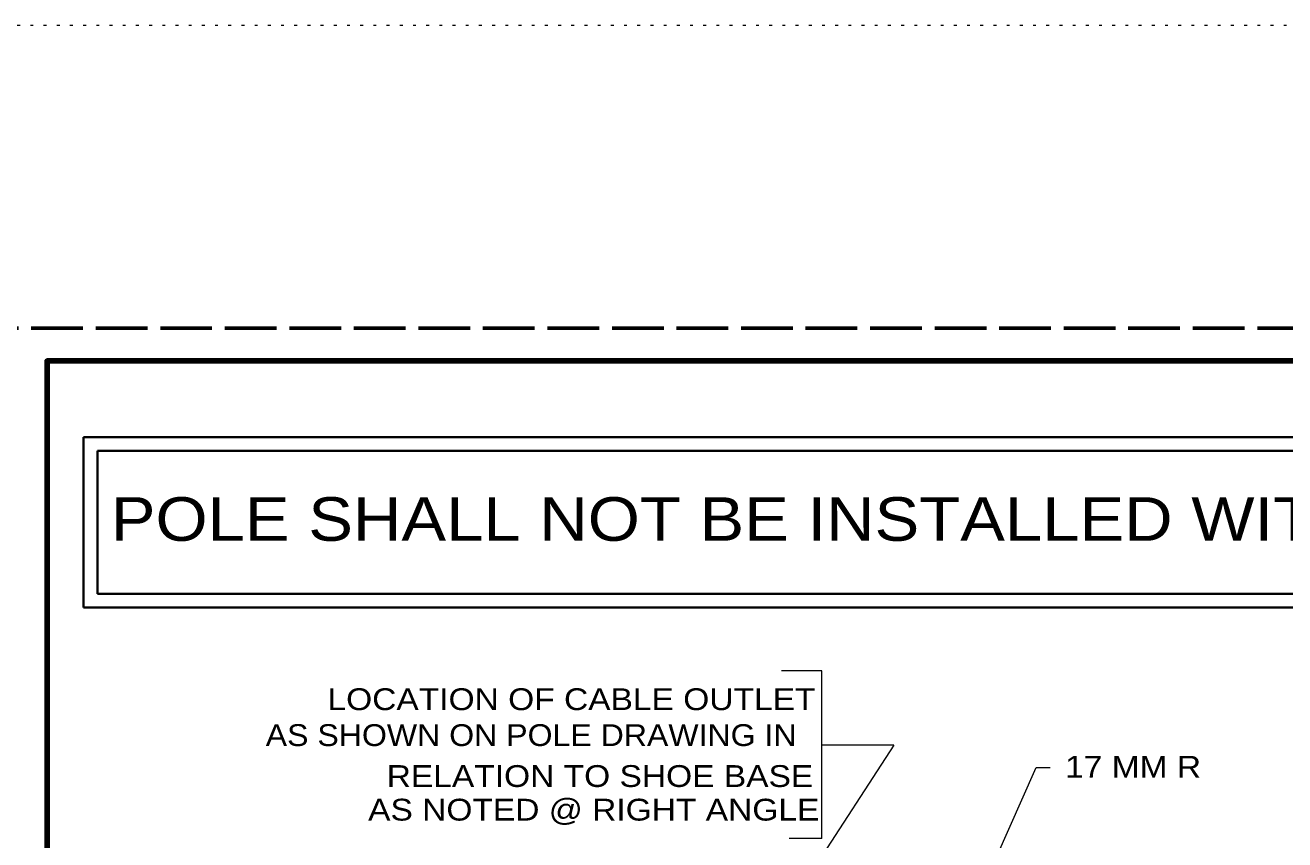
# Model space of a CAD drawing. Extents: x 312583 to 312854, y 144419 to 144597.
# Drawn here: x 312615.74 to 312659.66, y 144568.4 to 144596.78 of the extents above; entities that cross this region are included whole.
import ezdxf

# ---------------------------------------------------------------- set-up
doc = ezdxf.new("R2010")
doc.units = 0
doc.header["$LTSCALE"] = 0.3
doc.linetypes.add('DOTTED', pattern=[1.5, 0.3, -1.2])
doc.linetypes.add('LONG_DASHED', pattern=[7.5, 6, -1.5])
for name, color, linetype, lineweight in [('1', 7, 'Continuous', 40), ('2', 7, 'Continuous', 13), ('62', 7, 'DOTTED', 13), ('63', 7, 'LONG_DASHED', 60)]:
    doc.layers.add(name, color=color, linetype=linetype, lineweight=lineweight)

msp = doc.modelspace()

# ---------------------------------------------------------------- linework, layer by layer
at = {"layer": '1', "lineweight": 158}
msp.add_lwpolyline([(312616.5, 144423.1446), (312616.5, 144585.0846), (312849, 144585.0846)], dxfattribs=at)
at = {"layer": '2', "lineweight": 35}
for p, q in [((312617.7724, 144582.426), (312674.5206, 144582.426)), ((312617.7724, 144576.492), (312617.7724, 144582.426)), ((312618.2554, 144581.9507), (312674.0452, 144581.9507)), ((312618.2554, 144576.9673), (312618.2554, 144581.9507)), ((312618.2554, 144576.9673), (312674.0452, 144576.9673))]:
    msp.add_line(p, q, dxfattribs=at)
at = {"layer": '2'}
for p, q in [((312646.0243, 144571.696), (312640.9413, 144563.876)), ((312646.0243, 144571.696), (312643.5119, 144571.696)), ((312643.5119, 144568.4376), (312642.3772, 144568.4376))]:
    msp.add_line(p, q, dxfattribs=at)
at = {"layer": '2', "lineweight": 35}
msp.add_lwpolyline([(312617.7724, 144576.492), (312674.5206, 144576.492), (312674.5206, 144582.426)], dxfattribs=at)
at = {"layer": '2'}
for points in [[(312643.5119, 144568.4376), (312643.5119, 144574.2873), (312642.1089, 144574.2873)], [(312648.6693, 144565.7006), (312650.9923, 144570.914), (312651.4753, 144570.914)]]:
    msp.add_lwpolyline(points, dxfattribs=at)
at = {"layer": '62'}
msp.add_line((312601.2, 144596.7846), (312853.5, 144596.7846), dxfattribs=at)
at = {"layer": '63'}
msp.add_line((312851.75, 144586.2246), (312583.526, 144586.2246), dxfattribs=at)

# ---------------------------------------------------------------- texts
at = {"layer": '2'}
for s, height, width, p in [('POLE SHALL NOT BE INSTALLED WITHOUT ARM', 1.52, 1.15, (312618.7225, 144578.8155)), ('LOCATION OF CABLE OUTLET', 0.76, 1.15, (312626.278, 144572.9154)), ('AS SHOWN ON POLE DRAWING IN', 0.76, 1.1, (312624.1241, 144571.6633)), ('17 MM R', 0.76, 1.15, (312651.9966, 144570.5603)), ('RELATION TO SHOE BASE', 0.76, 1.15, (312628.3429, 144570.2373)), ('AS NOTED @ RIGHT ANGLE', 0.76, 1.15, (312627.6951, 144569.0653))]:
    msp.add_text(s, height=height, dxfattribs=dict(at, width=width)).set_placement(p)

doc.saveas('drawing.dxf')
